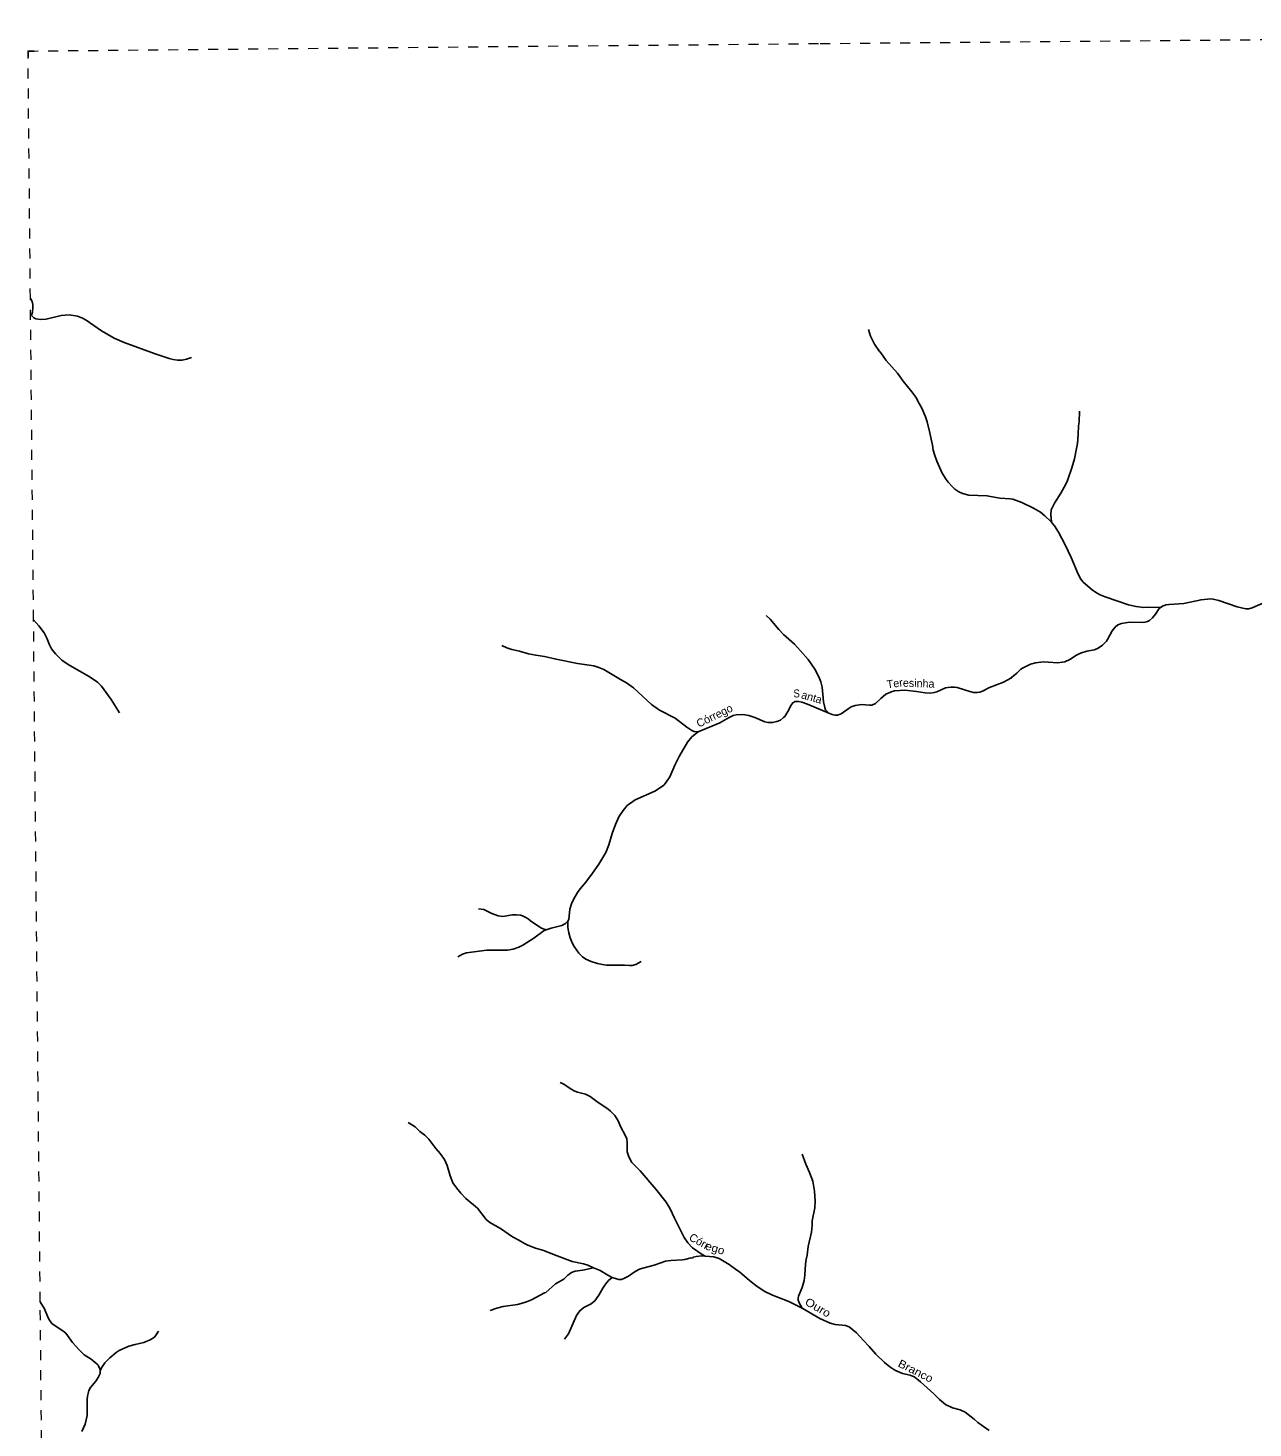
# Model space of a CAD drawing. Extents: x 344.9 to 371, y 7566.4 to 7594.3.
# Drawn here: x 344.88 to 357.12, y 7580.3 to 7594.29 of the extents above; entities that cross this region are included whole.
import ezdxf
from ezdxf.enums import TextEntityAlignment as Align

# ---------------------------------------------------------------- set-up
doc = ezdxf.new("R2010")
doc.units = 0
doc.header["$LTSCALE"] = 0.04
doc.linetypes.add('SHORT_DASHED', pattern=[2.7, 1.5, -1.2])
for name, color, linetype, lineweight in [('53', 7, 'SHORT_DASHED', 13), ('63', 7, 'Continuous', 25), ('7', 7, 'Continuous', 25)]:
    doc.layers.add(name, color=color, linetype=linetype, lineweight=lineweight)
doc.layers.add('61', color=7, linetype='Continuous')

msp = doc.modelspace()

# ---------------------------------------------------------------- linework, layer by layer
at = {"layer": '53'}
for points in [[(344.8794, 7594.0606), (352.795, 7594.1355), (363.1063, 7594.2268), (368.6638, 7594.2735), (368.8649, 7594.2752), (369.1643, 7594.2776), (369.9437, 7594.2841), (370.7361, 7594.2906)], [(345.1495, 7566.3822), (345.0274, 7578.8981), (345.0227, 7579.3763), (345.0014, 7581.5596), (344.9349, 7588.3752), (344.9036, 7591.5858), (344.8794, 7594.0606)]]:
    msp.add_lwpolyline(points, dxfattribs=at)
at = {"layer": '63'}
msp.add_lwpolyline([(344.941, 7594.0606), (344.8794, 7594.0606), (344.8794, 7593.9999)], dxfattribs=at)
at = {"layer": '7'}
for points in [[(345.4603, 7591.3696), (345.4254, 7591.3895), (345.3729, 7591.4117), (345.2896, 7591.422), (345.2118, 7591.4165), (345.0593, 7591.3815), (345.0037, 7591.3776), (344.9592, 7591.3831), (344.9386, 7591.3926), (344.9163, 7591.4133), (344.9155, 7591.4205), (344.9259, 7591.4491), (344.929, 7591.4983), (344.9274, 7591.5269), (344.9203, 7591.5571), (344.9036, 7591.5858)], [(346.5133, 7590.9972), (346.4632, 7590.9805), (346.4188, 7590.9718), (346.3743, 7590.9718), (346.3298, 7590.9781), (346.2901, 7590.9877), (346.1504, 7591.0337), (345.8407, 7591.1457), (345.7398, 7591.191), (345.6128, 7591.2632), (345.4603, 7591.3696)], [(353.2797, 7591.2783), (353.2987, 7591.2108), (353.3384, 7591.1314), (353.39, 7591.0583), (353.3972, 7591.0528), (353.398, 7591.0472), (353.4035, 7591.0433), (353.4551, 7590.9678), (353.5695, 7590.8392), (353.6267, 7590.7598), (353.7132, 7590.655), (353.7513, 7590.601), (353.7871, 7590.5374), (353.8117, 7590.4898), (353.8474, 7590.404), (353.8649, 7590.3532), (353.8895, 7590.2579), (353.9173, 7590.1198)], [(355.3888, 7590.462), (355.3856, 7590.3532), (355.3792, 7590.3151), (355.3752, 7590.2262), (355.3665, 7590.1372), (355.3593, 7590.0864), (355.3371, 7589.9848), (355.3101, 7589.8958), (355.2664, 7589.7688), (355.2498, 7589.7307), (355.2029, 7589.6417), (355.137, 7589.5401), (355.106, 7589.4742), (355.1005, 7589.4257), (355.1092, 7589.3542)], [(353.9173, 7590.1198), (353.9244, 7590.0721), (353.9371, 7590.0261), (353.961, 7589.9625), (354.0165, 7589.8402), (354.0547, 7589.7783), (354.0761, 7589.7497), (354.1213, 7589.7021), (354.1436, 7589.6822), (354.1817, 7589.6552), (354.2199, 7589.6377), (354.2834, 7589.6218), (354.4629, 7589.6147), (354.5931, 7589.5909), (354.6947, 7589.5845), (354.7201, 7589.5798), (354.8123, 7589.5472), (354.9266, 7589.4924)], [(354.9266, 7589.4924), (354.9965, 7589.4503), (355.0417, 7589.413), (355.1002, 7589.3579), (355.1092, 7589.3542)], [(355.1092, 7589.3542), (355.1155, 7589.3408), (355.1386, 7589.3146), (355.1767, 7589.251)], [(355.1767, 7589.251), (355.2458, 7589.124), (355.3038, 7588.9969), (355.3736, 7588.8318), (355.4014, 7588.7809), (355.4261, 7588.7523), (355.515, 7588.6753), (355.5571, 7588.6459), (355.5936, 7588.6253), (355.646, 7588.6038), (355.8779, 7588.5244), (355.9541, 7588.5069), (356.0304, 7588.4982), (356.0812, 7588.5014), (356.1984, 7588.4986)], [(356.1984, 7588.4986), (356.2225, 7588.5141), (356.2543, 7588.5244)], [(356.2543, 7588.5244), (356.2829, 7588.5292), (356.429, 7588.5387), (356.6037, 7588.5752), (356.6958, 7588.584), (356.7244, 7588.5824), (356.7816, 7588.5697), (356.9642, 7588.5038), (357.05, 7588.4855), (357.0817, 7588.4863), (357.1135, 7588.4942), (357.2422, 7588.5506), (357.2882, 7588.5641), (357.3486, 7588.5641), (357.4931, 7588.5443), (357.6408, 7588.5355), (357.7297, 7588.5236)], [(344.9349, 7588.3752), (344.9878, 7588.314), (345.0402, 7588.2457), (345.0688, 7588.1901), (345.0942, 7588.1234), (345.1156, 7588.0845), (345.153, 7588.0337), (345.2181, 7587.9733), (345.28, 7587.9281), (345.4849, 7587.8129), (345.5405, 7587.7764), (345.5731, 7587.751), (345.6143, 7587.7105), (345.6413, 7587.6756), (345.712, 7587.5771), (345.7938, 7587.4445)], [(352.2553, 7588.418), (352.2981, 7588.3807), (352.3847, 7588.2783), (352.4308, 7588.229), (352.5396, 7588.1313), (352.6007, 7588.0663), (352.6769, 7587.9789), (352.7428, 7587.8804), (352.7841, 7587.8058), (352.8032, 7587.7566), (352.8175, 7587.701), (352.8302, 7587.5549), (352.8413, 7587.4977), (352.8508, 7587.4755), (352.8827, 7587.4406)], [(356.1984, 7588.4986), (356.1844, 7588.4879), (356.1463, 7588.4315), (356.1161, 7588.395), (356.0883, 7588.3695), (356.0669, 7588.3584), (356.0415, 7588.3513), (356.0129, 7588.3489), (355.8859, 7588.3513), (355.808, 7588.3386), (355.7699, 7588.3235), (355.7429, 7588.3021), (355.7127, 7588.2664), (355.6682, 7588.1774), (355.6579, 7588.1623), (355.6182, 7588.1226), (355.5738, 7588.0916), (355.5365, 7588.0765), (355.4602, 7588.0623), (355.3967, 7588.0408), (355.3586, 7588.0202), (355.2919, 7587.9773), (355.2426, 7587.9558), (355.2172, 7587.9503), (355.1664, 7587.9455), (355.0775, 7587.9519)], [(350.3701, 7587.9384), (350.1573, 7587.9813), (350.0398, 7588.0091), (349.954, 7588.0202), (349.881, 7588.0353), (349.7905, 7588.0607), (349.7142, 7588.0773), (349.6634, 7588.0956), (349.6134, 7588.1187)], [(355.0775, 7587.9519), (355.0267, 7587.9551), (354.9488, 7587.9463), (354.8996, 7587.9328), (354.8766, 7587.9233), (354.8178, 7587.8931), (354.8003, 7587.8804), (354.7614, 7587.8431), (354.7074, 7587.7986), (354.7018, 7587.7891), (354.7003, 7587.7907), (354.628, 7587.7533), (354.4898, 7587.7002), (354.4184, 7587.6612), (354.393, 7587.6517), (354.3676, 7587.6485), (354.3294, 7587.6493), (354.2913, 7587.6573), (354.1643, 7587.697), (354.1389, 7587.7017), (354.1007, 7587.7025), (354.0738, 7587.7002), (354.0483, 7587.6938), (353.961, 7587.6557), (353.9356, 7587.6477), (353.8975, 7587.6422)], [(351.5753, 7587.255), (351.5374, 7587.2602), (351.5152, 7587.2698), (351.4636, 7587.3023), (351.3484, 7587.3912), (351.1888, 7587.4723), (351.1102, 7587.5302), (350.9308, 7587.6962), (350.8609, 7587.7446), (350.8005, 7587.7772), (350.6338, 7587.8772), (350.5845, 7587.8987), (350.5337, 7587.9146), (350.3701, 7587.9384)], [(353.8975, 7587.6422), (353.8466, 7587.6438), (353.7577, 7587.6589), (353.6418, 7587.6708), (353.5401, 7587.6636), (353.5147, 7587.6581), (353.4512, 7587.6311), (353.4012, 7587.5898), (353.3487, 7587.5397), (353.313, 7587.5223), (353.2876, 7587.5215), (353.2082, 7587.5278), (353.1447, 7587.5191), (353.1066, 7587.504), (353.0843, 7587.4913), (353.0057, 7587.4349), (352.9684, 7587.4206), (352.943, 7587.4214), (352.9159, 7587.4276), (352.8827, 7587.4406)], [(352.584, 7587.5572), (352.5467, 7587.5572), (352.5229, 7587.5461), (352.5014, 7587.5199), (352.484, 7587.477), (352.4419, 7587.4103), (352.4308, 7587.3976), (352.3982, 7587.3722), (352.3633, 7587.3571), (352.3204, 7587.3476), (352.2744, 7587.3476), (352.2442, 7587.3547), (352.1441, 7587.3984), (352.0838, 7587.419), (352.0218, 7587.4286), (351.9583, 7587.4262), (351.9281, 7587.4175), (351.8868, 7587.3984), (351.7938, 7587.3457), (351.5753, 7587.255)], [(352.8827, 7587.4406), (352.6698, 7587.5334), (352.6126, 7587.5525), (352.584, 7587.5572)], [(351.5753, 7587.255), (351.5144, 7587.2054), (351.4691, 7587.1515), (351.3873, 7587.0101), (351.3429, 7586.9212)], [(351.3429, 7586.9212), (351.2952, 7586.8052), (351.2508, 7586.7417), (351.2325, 7586.7226), (351.1912, 7586.6909), (351.1452, 7586.6631), (350.9458, 7586.5757), (350.868, 7586.5202), (350.8267, 7586.4701), (350.7854, 7586.4066), (350.7513, 7586.3304), (350.7187, 7586.2399), (350.6838, 7586.1255), (350.6536, 7586.0493), (350.5845, 7585.9333), (350.5194, 7585.8412)], [(350.5194, 7585.8412), (350.4535, 7585.7539), (350.3979, 7585.6872), (350.3701, 7585.6491), (350.3328, 7585.5855), (350.3113, 7585.5347), (350.2947, 7585.4839), (350.2833, 7585.3804), (350.2741, 7585.3628)], [(350.058, 7585.2759), (350.0287, 7585.2853), (350.0049, 7585.2972), (349.9024, 7585.3664), (349.8794, 7585.3854), (349.8556, 7585.4005), (349.8222, 7585.4156), (349.8, 7585.4219), (349.7603, 7585.4267), (349.7222, 7585.4251), (349.6253, 7585.4108), (349.5792, 7585.4156), (349.5157, 7585.4402), (349.4363, 7585.4791), (349.3831, 7585.4855)], [(350.2741, 7585.3628), (350.251, 7585.3409), (350.2129, 7585.3211), (350.1732, 7585.3084), (350.1065, 7585.2933), (350.058, 7585.2759)], [(351.0062, 7584.9582), (350.9546, 7584.9296), (350.9165, 7584.9193), (350.8911, 7584.9185), (350.8402, 7584.9232), (350.6608, 7584.924), (350.6211, 7584.9288), (350.5702, 7584.9399), (350.5067, 7584.9613), (350.4559, 7584.9828), (350.4202, 7585.0058), (350.3836, 7585.0416), (350.336, 7585.1091), (350.3161, 7585.1472), (350.2963, 7585.1964), (350.2836, 7585.2473), (350.2756, 7585.2981), (350.2741, 7585.3628)], [(350.058, 7585.2759), (350.0382, 7585.2687), (349.935, 7585.1916), (349.8238, 7585.1217), (349.7841, 7585.1035), (349.7269, 7585.0828), (349.6698, 7585.0741)], [(349.6698, 7585.0741), (349.4665, 7585.0717), (349.2632, 7585.0471), (349.2219, 7585.0336), (349.1766, 7585.005)], [(350.9156, 7582.9523), (350.8831, 7583.0079), (350.868, 7583.0588), (350.8688, 7583.1477), (350.8656, 7583.1858), (350.8489, 7583.2255), (350.8037, 7583.3049), (350.7759, 7583.3684), (350.7433, 7583.4209), (350.7021, 7583.4637), (350.6782, 7583.4836), (350.5631, 7583.5598), (350.4988, 7583.6106), (350.4495, 7583.6352), (350.3701, 7583.6535), (350.3447, 7583.6638), (350.3082, 7583.6829), (350.2359, 7583.7321), (350.1962, 7583.7488)], [(348.6779, 7583.3502), (348.7502, 7583.3065), (348.7962, 7583.2612), (348.8447, 7583.2231), (348.8844, 7583.1826), (348.9543, 7583.0913), (348.9979, 7583.0421), (349.0408, 7582.9793), (349.0678, 7582.9214), (349.0988, 7582.8173), (349.1266, 7582.7491), (349.1615, 7582.6982), (349.2036, 7582.6458), (349.2552, 7582.5918), (349.3712, 7582.4941), (349.4569, 7582.3814), (349.4951, 7582.3504), (349.603, 7582.29)], [(351.6454, 7582.0161), (351.6176, 7582.0312), (351.5199, 7582.0987), (351.4731, 7582.1487), (351.4358, 7582.2011), (351.3397, 7582.3933), (351.2968, 7582.4862), (351.2555, 7582.5537), (351.1547, 7582.6855), (350.9959, 7582.8658), (350.9156, 7582.9523)], [(352.6158, 7583.0341), (352.6515, 7582.9333), (352.6904, 7582.8523), (352.7222, 7582.7634), (352.7397, 7582.6649), (352.746, 7582.5648), (352.7413, 7582.4981), (352.7158, 7582.3663), (352.7158, 7582.3218), (352.7079, 7582.2551), (352.6777, 7582.1122), (352.6666, 7582.0233), (352.6571, 7581.982)], [(349.603, 7582.29), (349.7214, 7582.2083), (349.7857, 7582.1741), (349.8413, 7582.14), (349.8762, 7582.1241), (349.9524, 7582.0947), (350.0461, 7582.0669), (350.0477, 7582.0629), (350.0922, 7582.0487), (350.1684, 7582.0169), (350.3193, 7581.9605), (350.4305, 7581.9383), (350.475, 7581.924), (350.5322, 7581.8962)], [(350.8101, 7581.7826), (350.8355, 7581.7906), (350.8815, 7581.8152), (350.9466, 7581.8604), (350.9895, 7581.8843), (351.0229, 7581.8954), (351.1372, 7581.924), (351.2516, 7581.9637), (351.3024, 7581.9716), (351.4215, 7581.9764), (351.4437, 7581.9796), (351.5057, 7581.997), (351.5088, 7581.9946), (351.5255, 7582.0002), (351.5271, 7582.005), (351.5581, 7582.0105), (351.6137, 7582.0169), (351.6454, 7582.0161)], [(351.9647, 7581.8739), (351.8868, 7581.9327), (351.7852, 7581.9907), (351.7344, 7582.0066), (351.6454, 7582.0161)], [(352.6571, 7581.982), (352.6499, 7581.9343), (352.6436, 7581.8232), (352.6356, 7581.7707), (352.6166, 7581.7025), (352.5793, 7581.6135), (352.5761, 7581.5913), (352.5777, 7581.5738), (352.5904, 7581.5405), (352.611, 7581.5087), (352.6162, 7581.4946)], [(350.5322, 7581.8962), (350.4241, 7581.8755), (350.3479, 7581.8652), (350.3114, 7581.8525), (350.2756, 7581.8255), (350.2336, 7581.7842), (350.1518, 7581.7374), (350.0541, 7581.6524), (350.0414, 7581.6484), (349.9127, 7581.5778), (349.8619, 7581.5571), (349.8095, 7581.5404), (349.7714, 7581.5317), (349.6285, 7581.5103), (349.5649, 7581.4944), (349.499, 7581.4714)], [(350.7172, 7581.8018), (350.6822, 7581.7699), (350.6512, 7581.7342), (350.6258, 7581.6961), (350.5845, 7581.623), (350.5448, 7581.5682), (350.5067, 7581.5365), (350.4345, 7581.5007), (350.3931, 7581.4682), (350.3598, 7581.4198), (350.2796, 7581.2395), (350.2415, 7581.1839)], [(350.5322, 7581.8962), (350.5988, 7581.8716), (350.6735, 7581.8247), (350.7172, 7581.8018)], [(350.7172, 7581.8018), (350.7592, 7581.7866), (350.7846, 7581.7818), (350.8101, 7581.7826)], [(352.6162, 7581.4946), (352.4824, 7581.5603), (352.3188, 7581.623), (352.2426, 7581.6611), (352.1655, 7581.7096), (352.0893, 7581.7699), (351.9893, 7581.8565), (351.9647, 7581.8739)], [(345.0014, 7581.5596), (345.0458, 7581.4896), (345.0799, 7581.3991), (345.0942, 7581.3737), (345.1188, 7581.3419), (345.1498, 7581.3165), (345.2276, 7581.2681), (345.257, 7581.2451), (345.3237, 7581.1513), (345.3872, 7581.0799), (345.4412, 7581.029), (345.5103, 7580.9854), (345.5714, 7580.9362), (345.581, 7580.9242), (345.5979, 7580.8891), (345.6021, 7580.872)], [(353.228, 7581.172), (353.1589, 7581.2474), (353.0859, 7581.3094), (353.0478, 7581.3213), (352.9461, 7581.3316), (352.8953, 7581.3459), (352.7937, 7581.3919), (352.6162, 7581.4946)], [(346.1821, 7581.2633), (346.1615, 7581.2284), (346.144, 7581.2061), (346.1011, 7581.1783), (346.0376, 7581.1513), (345.9487, 7581.1323), (345.8867, 7581.1148), (345.7898, 7581.0719), (345.7597, 7581.0505), (345.6985, 7580.9989), (345.6485, 7580.9473), (345.6191, 7580.9084), (345.6021, 7580.872)], [(354.4835, 7580.2723), (354.3731, 7580.3509), (354.3366, 7580.3842), (354.2469, 7580.4541), (354.196, 7580.4771), (354.1198, 7580.4978), (354.0499, 7580.5327), (353.9879, 7580.5828), (353.9316, 7580.6399), (353.7982, 7580.7599), (353.7466, 7580.8003), (353.7339, 7580.8083), (353.6958, 7580.8234), (353.6195, 7580.8408), (353.5941, 7580.8504), (353.5433, 7580.8758), (353.4917, 7580.9099), (353.4401, 7580.952), (353.3527, 7581.0338), (353.286, 7581.1108), (353.228, 7581.172)], [(345.6021, 7580.872), (345.5992, 7580.8433), (345.5818, 7580.8004), (345.5572, 7580.7638), (345.5039, 7580.7003), (345.4889, 7580.6717), (345.4801, 7580.6431), (345.473, 7580.6146), (345.4714, 7580.586), (345.4722, 7580.4653), (345.469, 7580.4224), (345.4515, 7580.3366), (345.419, 7580.2604)]]:
    msp.add_lwpolyline(points, dxfattribs=at)

# ---------------------------------------------------------------- texts
at = {"layer": '61', "width": 0.9}
msp.add_text('S', height=0.08, dxfattribs=at).set_placement((352.5612, 7587.5994), align=Align.CENTER)
at = {"layer": '61'}
for s, rotation, p in [('Ter', 8.413, (353.5473, 7587.7001)), ('esinha', 358.081, (353.7796, 7587.7014)), ('anta', 343.842, (352.701, 7587.5635)), ('Córrego', 26.06, (351.7577, 7587.3812)), ('Córr', 330.602, (351.568, 7582.1282))]:
    msp.add_text(s, height=0.08, rotation=rotation, dxfattribs=at).set_placement(p, align=Align.CENTER)
for s, rotation, width, p in [('ego', 342.804, 1.1, (351.7339, 7582.0556)), ('Ouro', 330.093, 1.15, (352.7541, 7581.4669)), ('Branco', 333.416, 1.1, (353.733, 7580.8313))]:
    msp.add_text(s, height=0.08, rotation=rotation, dxfattribs=dict(at, width=width)).set_placement(p, align=Align.CENTER)

doc.saveas('drawing.dxf')
